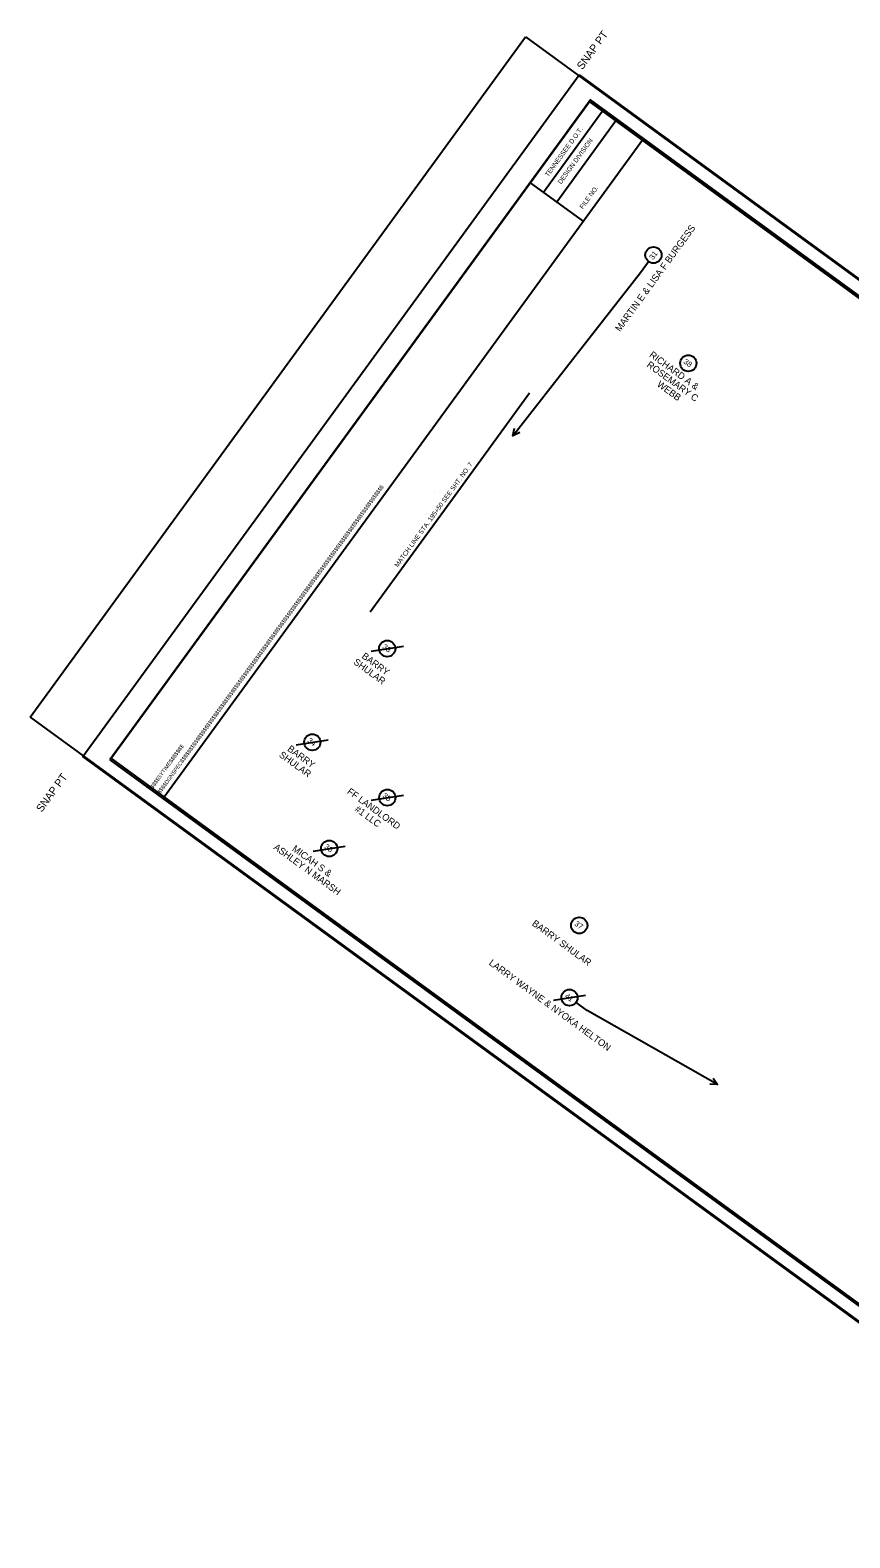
# Model space of a CAD drawing. Extents: x 2630958 to 2633078, y 566931 to 568943.
# Drawn here: x 2630958 to 2632018, y 566995 to 568943 of the extents above; entities that cross this region are included whole.
import ezdxf

# ---------------------------------------------------------------- set-up
doc = ezdxf.new("R2010")
doc.units = 0
for name, color, linetype in [('DESIGN - CENTERLINE - Proposed Text', 7, 'Continuous'), ('DESIGN - SCRATCH - User 1', 7, 'Continuous'), ('DESIGN - SHEET - Corner Text', 7, 'Continuous'), ('DESIGN - SHEET - Light Grid', 7, 'Continuous'), ('DESIGN - SHEET - Linework', 7, 'Continuous'), ('DESIGN - SHEET - Plot Shape', 7, 'Continuous'), ('SURVEY - PROPERTY - Owners', 7, 'Continuous'), ('SURVEY - PROPERTY - Tract Numbers', 7, 'Continuous')]:
    doc.layers.add(name, color=color, linetype=linetype)

msp = doc.modelspace()

# ---------------------------------------------------------------- linework, layer by layer
at = {"layer": 'DESIGN - CENTERLINE - Proposed Text'}
msp.add_lwpolyline([(2631397.5, 568191.1), (2631500.6, 568332.6), (2631603.6, 568474)], dxfattribs=at)
at = {"layer": 'DESIGN - SCRATCH - User 1'}
msp.add_line((2631481, 568346.8), (2631481, 568346.8), dxfattribs=at)
at = {"layer": 'DESIGN - SHEET - Light Grid'}
msp.add_lwpolyline([(2631061.2, 568000), (2632406.8, 567019.4), (2633028.1, 567872.1), (2631682.5, 568852.7)], close=True, dxfattribs=at)
at = {"layer": 'DESIGN - SHEET - Linework'}
for p, q in [((2630958.1, 568055.1), (2631598.5, 568933.9)), ((2631598.5, 568933.9), (2633053.2, 567873.8)), ((2631698.2, 568838.1), (2631621.7, 568733.1)), ((2631715.5, 568825.6), (2631638.9, 568720.6)), ((2630958.1, 568055.1), (2632412.8, 566995))]:
    msp.add_line(p, q, dxfattribs=at)
for points in [[(2631749.8, 568800.5), (2631681.1, 568850.6), (2631604.6, 568745.6), (2631673.3, 568695.6)], [(2631749.8, 568800.5), (2631131.4, 567952), (2632403.6, 567024.8), (2633022, 567873.4), (2631749.8, 568800.5)]]:
    msp.add_lwpolyline(points, dxfattribs=at)
at = {"layer": 'DESIGN - SHEET - Plot Shape'}
for points in [[(2631667.7, 568884.8), (2633041.6, 567883.5), (2632400, 567003.1), (2631026.1, 568004.3)], [(2631681.1, 568850.6), (2633022, 567873.4), (2632403.6, 567024.8), (2631062.7, 568002)]]:
    msp.add_lwpolyline(points, close=True, dxfattribs=at)
at = {"layer": 'SURVEY - PROPERTY - Tract Numbers'}
for p, q in [((2631399.1, 568140.5), (2631440.6, 568147)), ((2631302.1, 568019.5), (2631343.6, 568026)), ((2631399.1, 567948.1), (2631440.6, 567954.6)), ((2631324.1, 567882.2), (2631365.6, 567888.7)), ((2631634.7, 567689.6), (2631676.2, 567696.1))]:
    msp.add_line(p, q, dxfattribs=at)
for points in [[(2631747.4, 568629.5), (2631757.7, 568643.7)], [(2631582.2, 568418.7), (2631747.4, 568629.5)], [(2631591.1, 568422.9), (2631582.2, 568418.7), (2631584.2, 568428.3)], [(2631678.1, 567676.4), (2631663.9, 567686.7)], [(2631846.7, 567580.6), (2631678.1, 567676.4)], [(2631841.2, 567588.7), (2631846.7, 567580.6), (2631836.9, 567581.1)]]:
    msp.add_lwpolyline(points, dxfattribs=at)
for centre in [(2631763.9, 568652.1), (2631809, 568512.3), (2631419.8, 568143.8), (2631322.9, 568022.8), (2631419.9, 567951.3), (2631344.8, 567885.5), (2631668, 567786.2), (2631655.4, 567692.9)]:
    msp.add_circle(centre, 10.5, dxfattribs=at)

# ---------------------------------------------------------------- texts
at = {"layer": 'DESIGN - CENTERLINE - Proposed Text'}
msp.add_text('MATCH LINE STA. 195+50 SEE SHT. NO. 7', height=6, rotation=53.918, dxfattribs=at).set_placement((2631433.5, 568248.2))
at = {"layer": 'DESIGN - SHEET - Corner Text'}
for s, height, p in [('  SNAP PT', 10, (2631667.7, 568884.8)), ('TENNESSEE D.O.T.', 6, (2631628, 568752.7)), ('DESIGN DIVISION', 6, (2631644.5, 568743.2)), ('FILE NO.', 6, (2631672.7, 568711)), ('$$$$DGNSPEC$$$$$$$$$$$$$$$$$$$$$$$$$$$$$$$$$$$$$$$$$$$$$$$$$$$$$$$$$$$$$$$$$$$$$$$$$$$$$$$$$$$$$$$$$$$$$$$$$$$$$$$$$$$$$$$$$$$', 5.0001, (2631126.3, 567955.7)), ('$$$$SYTIME$$$$$$$', 5, (2631116.9, 567962.5)), ('SNAP PT  ', 10, (2630973.1, 567931.6))]:
    msp.add_text(s, height=height, rotation=53.918, dxfattribs=at).set_placement(p)
at = {"layer": 'SURVEY - PROPERTY - Owners'}
for s, rotation, p in [('MARTIN E & LISA F BURGESS', 53.918, (2631720.7, 568552.5)), ('ROSEMARY C', 323.918, (2631754.4, 568508.6)), ('RICHARD A &', 323.918, (2631757.8, 568521.5)), ('WEBB', 323.918, (2631767.7, 568483.4)), ('SHULAR', 323.918, (2631375.2, 568124.7)), ('BARRY', 323.918, (2631386, 568132.3)), ('SHULAR', 323.918, (2631279.1, 568004.8)), ('BARRY', 323.918, (2631289.9, 568012.5)), ('FF LANDLORD', 323.918, (2631367.1, 567957.3)), ('#1 LLC', 323.918, (2631377, 567934.6)), ('ASHLEY N MARSH', 323.918, (2631272.1, 567885.4)), ('MICAH S &', 323.918, (2631296, 567883.4)), ('BARRY SHULAR', 323.918, (2631606.1, 567786.9)), ('LARRY WAYNE & NYOKA HELTON', 323.918, (2631550.4, 567736))]:
    msp.add_text(s, height=8.75, rotation=rotation, dxfattribs=at).set_placement(p)
at = {"layer": 'SURVEY - PROPERTY - Tract Numbers'}
for s, rotation, p in [('31', 53.918, (2631763.4, 568645.4)), ('38', 323.918, (2631802, 568513)), ('33', 323.918, (2631412.9, 568144.5)), ('34', 323.918, (2631315.9, 568023.5)), ('35', 323.918, (2631413, 567952.1)), ('36', 323.918, (2631337.8, 567886.3)), ('37', 323.918, (2631661.1, 567786.9)), ('41', 323.918, (2631648.7, 567693.4))]:
    msp.add_text(s, height=7, rotation=rotation, dxfattribs=at).set_placement(p)

doc.saveas('drawing.dxf')
